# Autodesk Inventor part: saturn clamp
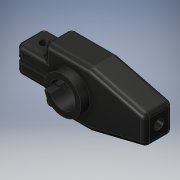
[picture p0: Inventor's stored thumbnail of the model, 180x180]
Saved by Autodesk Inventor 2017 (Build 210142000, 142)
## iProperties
Created: 2016-05
Part Number: saturn clamp
Material: Generic
Document SubType Name: Modeling
Designer: Stan
Density: 1 g/cm^3
Appearance: Glossy - Black
Author: Stan
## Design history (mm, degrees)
sketch "Sketch1"
  geometry: L1 (-9.525, 9.525)-(6.35, 9.525); L2 (6.35, -9.463)-(-9.525, -9.463); L3 (25.4, 4.763)-(25.4, -4.763); L4 (25.4, -4.763)-(6.35, -9.463); L5 (25.4, 4.763)-(6.35, 9.525); L6 (-9.525, 9.525)-(-9.525, 4.763); L7 (-9.525, 4.763)-(-19.05, 4.762); L8 (-19.05, -4.7)-(-9.525, -4.7); L9 (-9.525, -4.7)-(-9.525, -9.463); L10 (-4.299, 0.762)-(-19.05, 0.762); L11 (-4.299, -0.762)-(-19.05, -0.762); L12 (-19.05, -4.7)-(-19.05, -0.762); L13 (-19.05, 0.762)-(-19.05, 4.762); A1 r 4.366 centre (0, 0) between (-4.299, -0.762) and (-4.299, 0.762); 1 further point
  constraints: 26 end point, 4 perpendicular, 2 point on circle, 2 point on line, 2 vertical, 1 centre point, 1 coincident, 1 horizontal, 1 parallel
  dimensions: "d1" = 9.525 distance from line of L1 point (0, 0); "d2" = 25.4 horizontal distance of L3.end point (0, 0); "d4" = 9.525 distance of L3.start L3.end; "d5" = 4.7625 vertical distance of point (0, 0) L3.start; "d7" = 8.73125 diameter of A1; "d8" = 19.05 horizontal distance of L8.start point (0, 0); "d11" = 9.525 distance from line of point (0, 0) L6; "d12" = 19.05 distance from line of point (0, 0) L13; "d14" = 1.524 distance between parallel lines of L11 L10; "d15" = 0.762 distance from line of L10 point (0, 0); "d16" = 15.875 distance of L1.start L1.end; "d17" = 15.875 distance of L2.start L2.end; "d18" = 4.7625 distance between parallel lines of L2 L8; "d19" = 4.7625 distance between parallel lines of L7 L1
extrude "Extrusion1" new body sketch "Sketch1" distance "d20" = 9.525; taper "d21" = 0 deg
fillet "Fillet1" dims "d22" = 1.5875
sketch "Sketch2"
  geometry: C1 r 1.587 at (3.175, 3.519); 1 further point
  constraints: 1 centre point
  dimensions: "d23" = 3.175 diameter of C1
extrude "Extrusion2" cut sketch "Sketch2" distance "d24" = 15.875; taper "d25" = 0 deg
sketch "Sketch3"
  geometry: L1 (-1.587, 6.35)-(-1.588, 0) reference; C1 r 1.587 at (3.492, 3.175); 1 further point
  constraints: 1 centre point
  dimensions: "d26" = 3.175 diameter of C1; "d27" = 5.08 distance from line of C1.centre L1
extrude "Extrusion3" cut sketch "Sketch3" distance "d28" = 9.525; taper "d29" = 0 deg
fillet "Fillet2" dims "d30" = 1.5875
fillet "Fillet3" dims "d31" = 1.5875
sketch "Sketch4"
  geometry: L1 (-4.299, 0.762)-(-6.304, 0.762); L2 (-17.462, 0.762)-(-4.299, 0.762) reference; L3 (-4.136, -1.397)-(-6.194, -1.397); A1 r 6.35 centre (0, 0) between (-6.194, -1.397) and (-6.304, 0.762); A2 r 4.366 centre (0, 0) between (-4.136, -1.397) and (-4.299, 0.762); 1 further point
  constraints: 5 end point, 4 point on circle, 2 centre point, 2 coincident, 1 parallel, 1 point on line
  dimensions: "d32" = 12.7 diameter of A1
extrude "Extrusion4" join sketch "Sketch4" distance "d33" = 3.175; taper "d34" = 0 deg
body "Solid1"
